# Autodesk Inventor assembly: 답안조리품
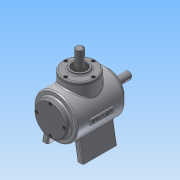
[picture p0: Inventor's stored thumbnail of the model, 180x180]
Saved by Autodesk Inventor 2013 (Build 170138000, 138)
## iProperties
Created: 2015-01
Part Number: 답안조리품
Document SubType Name: Assembly
Designer: Administrator
Author: Administrator
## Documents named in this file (15)
- C:\Users\Administrator\Desktop\450106V1021\450106V1021\답안조리품.iam
- C:\Users\Administrator\Desktop\450106V1021\450106V1021\본체.ipt
- C:\Users\Administrator\Desktop\450106V1021\450106V1021\M4.ipt
- C:\Users\Administrator\Desktop\450106V1021\450106V1021\메인 베벨기어.ipt
- C:\Users\Administrator\Desktop\450106V1021\450106V1021\메인 축.ipt
- 메인 축.ipt
- C:\Users\Administrator\Desktop\450106V1021\450106V1021\베어링 6203.ipt
- C:\Users\Administrator\Desktop\450106V1021\450106V1021\서브 베벨기어.ipt
- C:\Users\Administrator\Desktop\450106V1021\450106V1021\서브 축.ipt
- 서브 축.ipt
- C:\Users\Administrator\Desktop\450106V1021\450106V1021\오일실.ipt
- C:\Users\Administrator\Desktop\450106V1021\450106V1021\커버.ipt
- C:\Users\Administrator\Desktop\450106V1021\450106V1021\커버2.ipt
- C:\Users\Administrator\Desktop\450106V1021\450106V1021\키 4x4.ipt
- C:\Users\Administrator\Desktop\450106V1021\450106V1021\키 5x5.ipt
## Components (12 placed, 1 different names)
1. M4:2
2. M4:4
3. M4:5
4. M4:6
5. M4:1
6. M4:7
7. M4:8
8. M4:9
9. M4:3
10. M4:10
11. M4:11
12. M4:12
